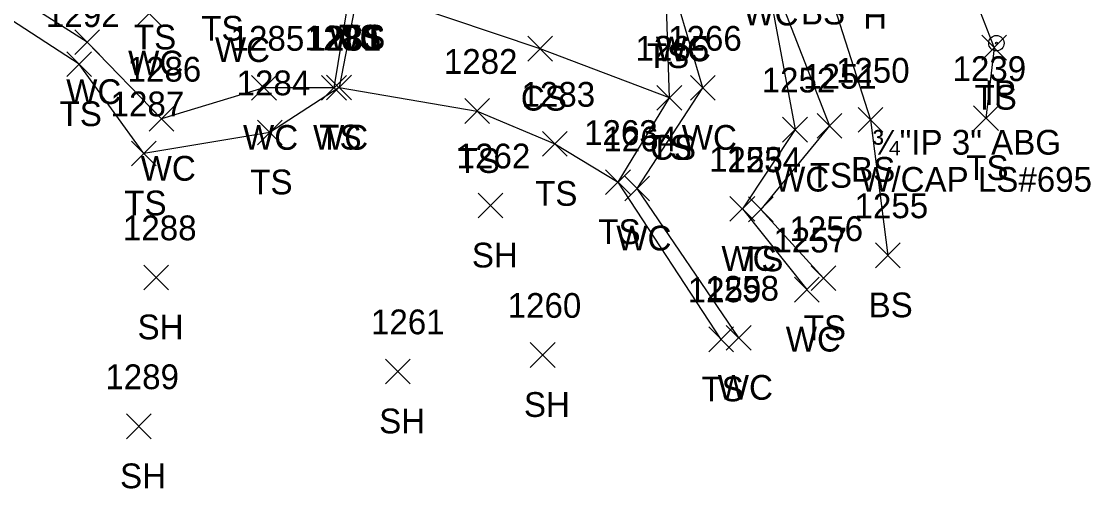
# Model space of a CAD drawing. Extents: x 1514253 to 1516033, y 782541 to 785002.
# Drawn here: x 1515367.9 to 1515454.3, y 782596.5 to 782634.2 of the extents above; entities that cross this region are included whole.
import ezdxf

# ---------------------------------------------------------------- set-up
doc = ezdxf.new("R2010")
doc.units = 0
for name, color, linetype in [('L_A', 7, 'Continuous'), ('L_I', 7, 'Continuous'), ('L_TIC', 7, 'Continuous'), ('LAWE', 7, 'Continuous'), ('LELB', 7, 'Continuous'), ('M_A', 7, 'Continuous'), ('M_C', 7, 'Continuous'), ('MPIR', 7, 'Continuous')]:
    doc.layers.add(name, color=color, linetype=linetype)

msp = doc.modelspace()

# ---------------------------------------------------------------- linework, layer by layer
at = {"layer": 'L_TIC'}
for points in [[(1515377.24, 782633.81), (1515379.24, 782635.81)], [(1515379.24, 782633.81), (1515377.24, 782635.81)], [(1515372.238, 782631.504), (1515374.238, 782633.504)], [(1515374.238, 782631.504), (1515372.238, 782633.504)], [(1515408.835, 782630.974), (1515410.835, 782632.974)], [(1515410.835, 782630.974), (1515408.835, 782632.974)], [(1515445.525, 782631.051), (1515447.525, 782633.051)], [(1515447.525, 782631.051), (1515445.525, 782633.051)], [(1515371.602, 782629.72), (1515373.602, 782631.72)], [(1515373.602, 782629.72), (1515371.602, 782631.72)], [(1515386.524, 782627.807), (1515388.524, 782629.807)], [(1515388.524, 782627.807), (1515386.524, 782629.807)], [(1515392.182, 782627.813), (1515394.182, 782629.813)], [(1515394.182, 782627.813), (1515392.182, 782629.813)], [(1515392.589, 782627.83), (1515394.589, 782629.83)], [(1515394.589, 782627.83), (1515392.589, 782629.83)], [(1515392.589, 782627.83), (1515394.589, 782629.83)], [(1515394.589, 782627.83), (1515392.589, 782629.83)], [(1515421.974, 782627.809), (1515423.974, 782629.809)], [(1515423.974, 782627.809), (1515421.974, 782629.809)], [(1515419.279, 782627.005), (1515421.279, 782629.005)], [(1515421.279, 782627.005), (1515419.279, 782629.005)], [(1515419.279, 782627.005), (1515421.279, 782629.005)], [(1515421.279, 782627.005), (1515419.279, 782629.005)], [(1515403.753, 782625.941), (1515405.753, 782627.941)], [(1515405.753, 782625.941), (1515403.753, 782627.941)], [(1515378.253, 782625.313), (1515380.253, 782627.313)], [(1515380.253, 782625.313), (1515378.253, 782627.313)], [(1515435.521, 782625.225), (1515437.521, 782627.225)], [(1515437.521, 782625.225), (1515435.521, 782627.225)], [(1515444.859, 782625.361), (1515446.859, 782627.361)], [(1515446.859, 782625.361), (1515444.859, 782627.361)], [(1515387.008, 782624.21), (1515389.008, 782626.21)], [(1515389.008, 782624.21), (1515387.008, 782626.21)], [(1515429.432, 782624.437), (1515431.432, 782626.437)], [(1515431.432, 782624.437), (1515429.432, 782626.437)], [(1515432.214, 782624.745), (1515434.214, 782626.745)], [(1515434.214, 782624.745), (1515432.214, 782626.745)], [(1515410.024, 782623.286), (1515412.024, 782625.286)], [(1515412.024, 782623.286), (1515410.024, 782625.286)], [(1515376.827, 782622.514), (1515378.827, 782624.514)], [(1515378.827, 782622.514), (1515376.827, 782624.514)], [(1515415.13, 782620.2), (1515417.13, 782622.2)], [(1515417.13, 782620.2), (1515415.13, 782622.2)], [(1515416.686, 782619.679), (1515418.686, 782621.679)], [(1515418.686, 782619.679), (1515416.686, 782621.679)], [(1515404.833, 782618.305), (1515406.833, 782620.305)], [(1515406.833, 782618.305), (1515404.833, 782620.305)], [(1515425.178, 782618.034), (1515427.178, 782620.034)], [(1515427.178, 782618.034), (1515425.178, 782620.034)], [(1515426.667, 782617.999), (1515428.667, 782619.999)], [(1515428.667, 782617.999), (1515426.667, 782619.999)], [(1515436.935, 782614.284), (1515438.935, 782616.284)], [(1515438.935, 782614.284), (1515436.935, 782616.284)], [(1515377.823, 782612.503), (1515379.823, 782614.503)], [(1515379.823, 782612.503), (1515377.823, 782614.503)], [(1515431.728, 782612.436), (1515433.728, 782614.436)], [(1515433.728, 782612.436), (1515431.728, 782614.436)], [(1515430.378, 782611.516), (1515432.378, 782613.516)], [(1515432.378, 782611.516), (1515430.378, 782613.516)], [(1515424.881, 782607.624), (1515426.881, 782609.624)], [(1515426.881, 782607.624), (1515424.881, 782609.624)], [(1515423.462, 782607.5), (1515425.462, 782609.5)], [(1515425.462, 782607.5), (1515423.462, 782609.5)], [(1515409.04, 782606.24), (1515411.04, 782608.24)], [(1515411.04, 782606.24), (1515409.04, 782608.24)], [(1515397.345, 782604.912), (1515399.345, 782606.912)], [(1515399.345, 782604.912), (1515397.345, 782606.912)], [(1515376.409, 782600.479), (1515378.409, 782602.479)], [(1515378.409, 782600.479), (1515376.409, 782602.479)]]:
    msp.add_lwpolyline(points, dxfattribs=at)
at = {"layer": 'LAWE'}
for points in [[(1515305.221, 782658.389), (1515309.247, 782657.829), (1515309.37, 782656.024), (1515310.661, 782652.237), (1515328.158, 782651.8), (1515339.372, 782649.611), (1515359.133, 782646.008), (1515370.291, 782640.974), (1515378.24, 782634.81), (1515385.256, 782635.895), (1515388.599, 782640.179), (1515389.121, 782646.36), (1515386.777, 782649.906), (1515390.568, 782651.945), (1515397.927, 782652.705), (1515407.459, 782649.219), (1515414.933, 782648.068), (1515419.945, 782646.777), (1515424.071, 782644.52), (1515427.947, 782638.847), (1515430.432, 782625.437), (1515426.178, 782619.034), (1515431.378, 782612.516)], [(1515425.881, 782608.624), (1515417.686, 782620.679), (1515422.974, 782628.809), (1515420.872, 782635.955), (1515417.164, 782641.13), (1515411.117, 782642.694), (1515398.91, 782647.419), (1515394.909, 782646.476), (1515394.422, 782644.041), (1515394.489, 782636.861), (1515393.182, 782628.813), (1515387.524, 782628.807), (1515379.253, 782626.313), (1515373.238, 782632.504), (1515362.112, 782639.578)]]:
    msp.add_lwpolyline(points, dxfattribs=at)
at = {"layer": 'LELB'}
for points in [[(1515310.163, 782657.372), (1515310.383, 782655.934), (1515311.738, 782653.239), (1515327.12, 782652.556), (1515340.38, 782650.599), (1515359.526, 782647.53), (1515371.713, 782643.995), (1515378.608, 782636.912), (1515384.051, 782637.622), (1515387.007, 782640.366), (1515387.011, 782646.011), (1515386.077, 782649.544), (1515388.534, 782653.757), (1515398.392, 782653.907), (1515407.552, 782650.359), (1515415.675, 782649.762), (1515419.247, 782648.751), (1515425.267, 782646.15), (1515433.214, 782625.745), (1515427.667, 782618.999), (1515432.728, 782613.436)], [(1515426.363, 782652.769), (1515428.334, 782647.754), (1515432.468, 782638.929), (1515436.521, 782626.225), (1515437.935, 782615.284)], [(1515448.667, 782652.433), (1515435.233, 782652.676), (1515441.048, 782646.115), (1515446.525, 782632.051), (1515445.859, 782626.361)], [(1515424.462, 782608.5), (1515416.13, 782621.2), (1515420.279, 782628.005), (1515420.055, 782635.411), (1515415.778, 782639.443), (1515407.458, 782642.731), (1515398.549, 782645.643), (1515395.171, 782636.9), (1515393.589, 782628.83), (1515388.008, 782625.21), (1515377.827, 782623.514), (1515372.602, 782630.72), (1515360.567, 782638.564)], [(1515420.279, 782628.005), (1515409.835, 782631.974), (1515395.171, 782636.9)], [(1515393.589, 782628.83), (1515404.753, 782626.941), (1515411.024, 782624.286)], [(1515411.024, 782624.286), (1515416.13, 782621.2)]]:
    msp.add_lwpolyline(points, dxfattribs=at)
at = {"layer": 'MPIR'}
for radius in [0.625, 0.0833]:
    msp.add_circle((1515446.704, 782632.416), radius, dxfattribs=at)

# ---------------------------------------------------------------- texts
at = {"layer": 'L_A'}
for s, p in [('WC', (1515426.254, 782633.847)), ('BS', (1515430.909, 782633.929)), ('H', (1515435.941, 782633.581)), ('TS', (1515377.017, 782631.912)), ('TS', (1515382.46, 782632.622)), ('WC', (1515392.796, 782631.861)), ('TS', (1515393.581, 782631.9)), ('CS', (1515393.612, 782631.9)), ('WC', (1515419.179, 782630.955)), ('WC', (1515383.563, 782630.895)), ('TS', (1515418.464, 782630.411)), ('WC', (1515376.547, 782629.81)), ('WC', (1515371.545, 782627.504)), ('CS', (1515408.276, 782626.974)), ('TS', (1515444.934, 782627.051)), ('TS', (1515371.012, 782625.72)), ('WC', (1515385.831, 782623.807)), ('WC', (1515391.489, 782623.813)), ('TS', (1515391.999, 782623.83)), ('TS', (1515391.999, 782623.83)), ('WC', (1515421.281, 782623.809)), ('TS', (1515418.688, 782623.005)), ('CS', (1515418.72, 782623.005)), ('TS', (1515403.162, 782621.941)), ('WC', (1515377.56, 782621.313)), ('TS', (1515431.623, 782620.745)), ('BS', (1515434.962, 782621.225)), ('TS', (1515444.268, 782621.361)), ('TS', (1515386.418, 782620.21)), ('WC', (1515428.739, 782620.437)), ('TS', (1515409.434, 782619.286)), ('TS', (1515376.237, 782618.514)), ('TS', (1515414.539, 782616.2)), ('WC', (1515415.993, 782615.679)), ('SH', (1515404.321, 782614.305)), ('WC', (1515424.485, 782614.034)), ('TS', (1515426.076, 782613.999)), ('BS', (1515436.376, 782610.284)), ('SH', (1515377.311, 782608.503)), ('TS', (1515431.137, 782608.436)), ('WC', (1515429.685, 782607.516)), ('TS', (1515422.872, 782603.5)), ('WC', (1515424.189, 782603.624)), ('SH', (1515408.528, 782602.24)), ('SH', (1515396.833, 782600.912)), ('SH', (1515375.897, 782596.479))]:
    msp.add_text(s, height=2, dxfattribs=at).set_placement(p)
at = {"layer": 'L_I'}
for s, p in [('1292', (1515369.91, 782633.72)), ('1285', (1515384.831, 782631.807)), ('1280', (1515390.81, 782631.83)), ('1280', (1515390.81, 782631.83)), ('1281', (1515391.056, 782631.813)), ('1266', (1515420.178, 782631.809)), ('1265', (1515417.539, 782631.005)), ('1265', (1515417.539, 782631.005)), ('1286', (1515376.505, 782629.313)), ('1282', (1515402.06, 782629.941)), ('1250', (1515433.742, 782629.225)), ('1239', (1515443.158, 782629.361)), ('1252', (1515427.739, 782628.437)), ('1251', (1515431.088, 782628.745)), ('1284', (1515385.315, 782628.21)), ('1283', (1515408.331, 782627.286)), ('1287', (1515375.134, 782626.514)), ('1263', (1515413.389, 782624.2)), ('1264', (1515414.946, 782623.679)), ('1262', (1515403.092, 782622.305)), ('1253', (1515423.485, 782622.034)), ('1254', (1515424.974, 782621.999)), ('1255', (1515435.242, 782618.284)), ('1288', (1515376.13, 782616.503)), ('1256', (1515429.98, 782616.436)), ('1257', (1515428.685, 782615.516)), ('1259', (1515421.761, 782611.5)), ('1258', (1515423.189, 782611.624)), ('1260', (1515407.213, 782610.24)), ('1261', (1515396.171, 782608.912)), ('1289', (1515374.708, 782604.479))]:
    msp.add_text(s, height=2, dxfattribs=at).set_placement(p)
at = {"layer": 'M_A'}
msp.add_text('IP', height=2, dxfattribs=at).set_placement((1515445.752, 782627.416))
at = {"layer": 'M_C'}
for s, p in [('¾"IP 3" ABG', (1515436.649, 782623.416)), ('W/CAP LS#695', (1515435.696, 782620.416))]:
    msp.add_text(s, height=2, dxfattribs=at).set_placement(p)

doc.saveas('drawing.dxf')
